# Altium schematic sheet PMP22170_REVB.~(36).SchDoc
size 431 x 279 mm; Date: Not shown in title block; ApprovedBy: Not shown in title block; CheckedBy: Not shown in title block; Author: Not shown in title block; CompanyName: Not shown in title block; Engineer: Not shown in title block; Organization: Not shown in title block; Address1: Not shown in title block; Address2: Not shown in title block; Address3: Not shown in title block; Address4: Not shown in title block; DocumentNumber: 1; Revision: Use project parameter SCH_Rev; SheetNumber: 1; SheetTotal: 1; PageSetup: Record=PageOptions¦CenterHorizontal=True¦CenterVertical=True¦PrintScale=1.00¦XCorrection=1.00¦YCorrection=1.00¦PrintKind=0¦BorderSize=5000000¦LeftOffset=0¦BottomOffset=0¦Orientation=2¦PaperLength=1000¦PaperWidth=1000¦Scale=100¦PaperSource=15¦PrintQuality=600¦MediaType=1¦DitherType=10¦PaperKind=Letter¦PrintScaleMode=1
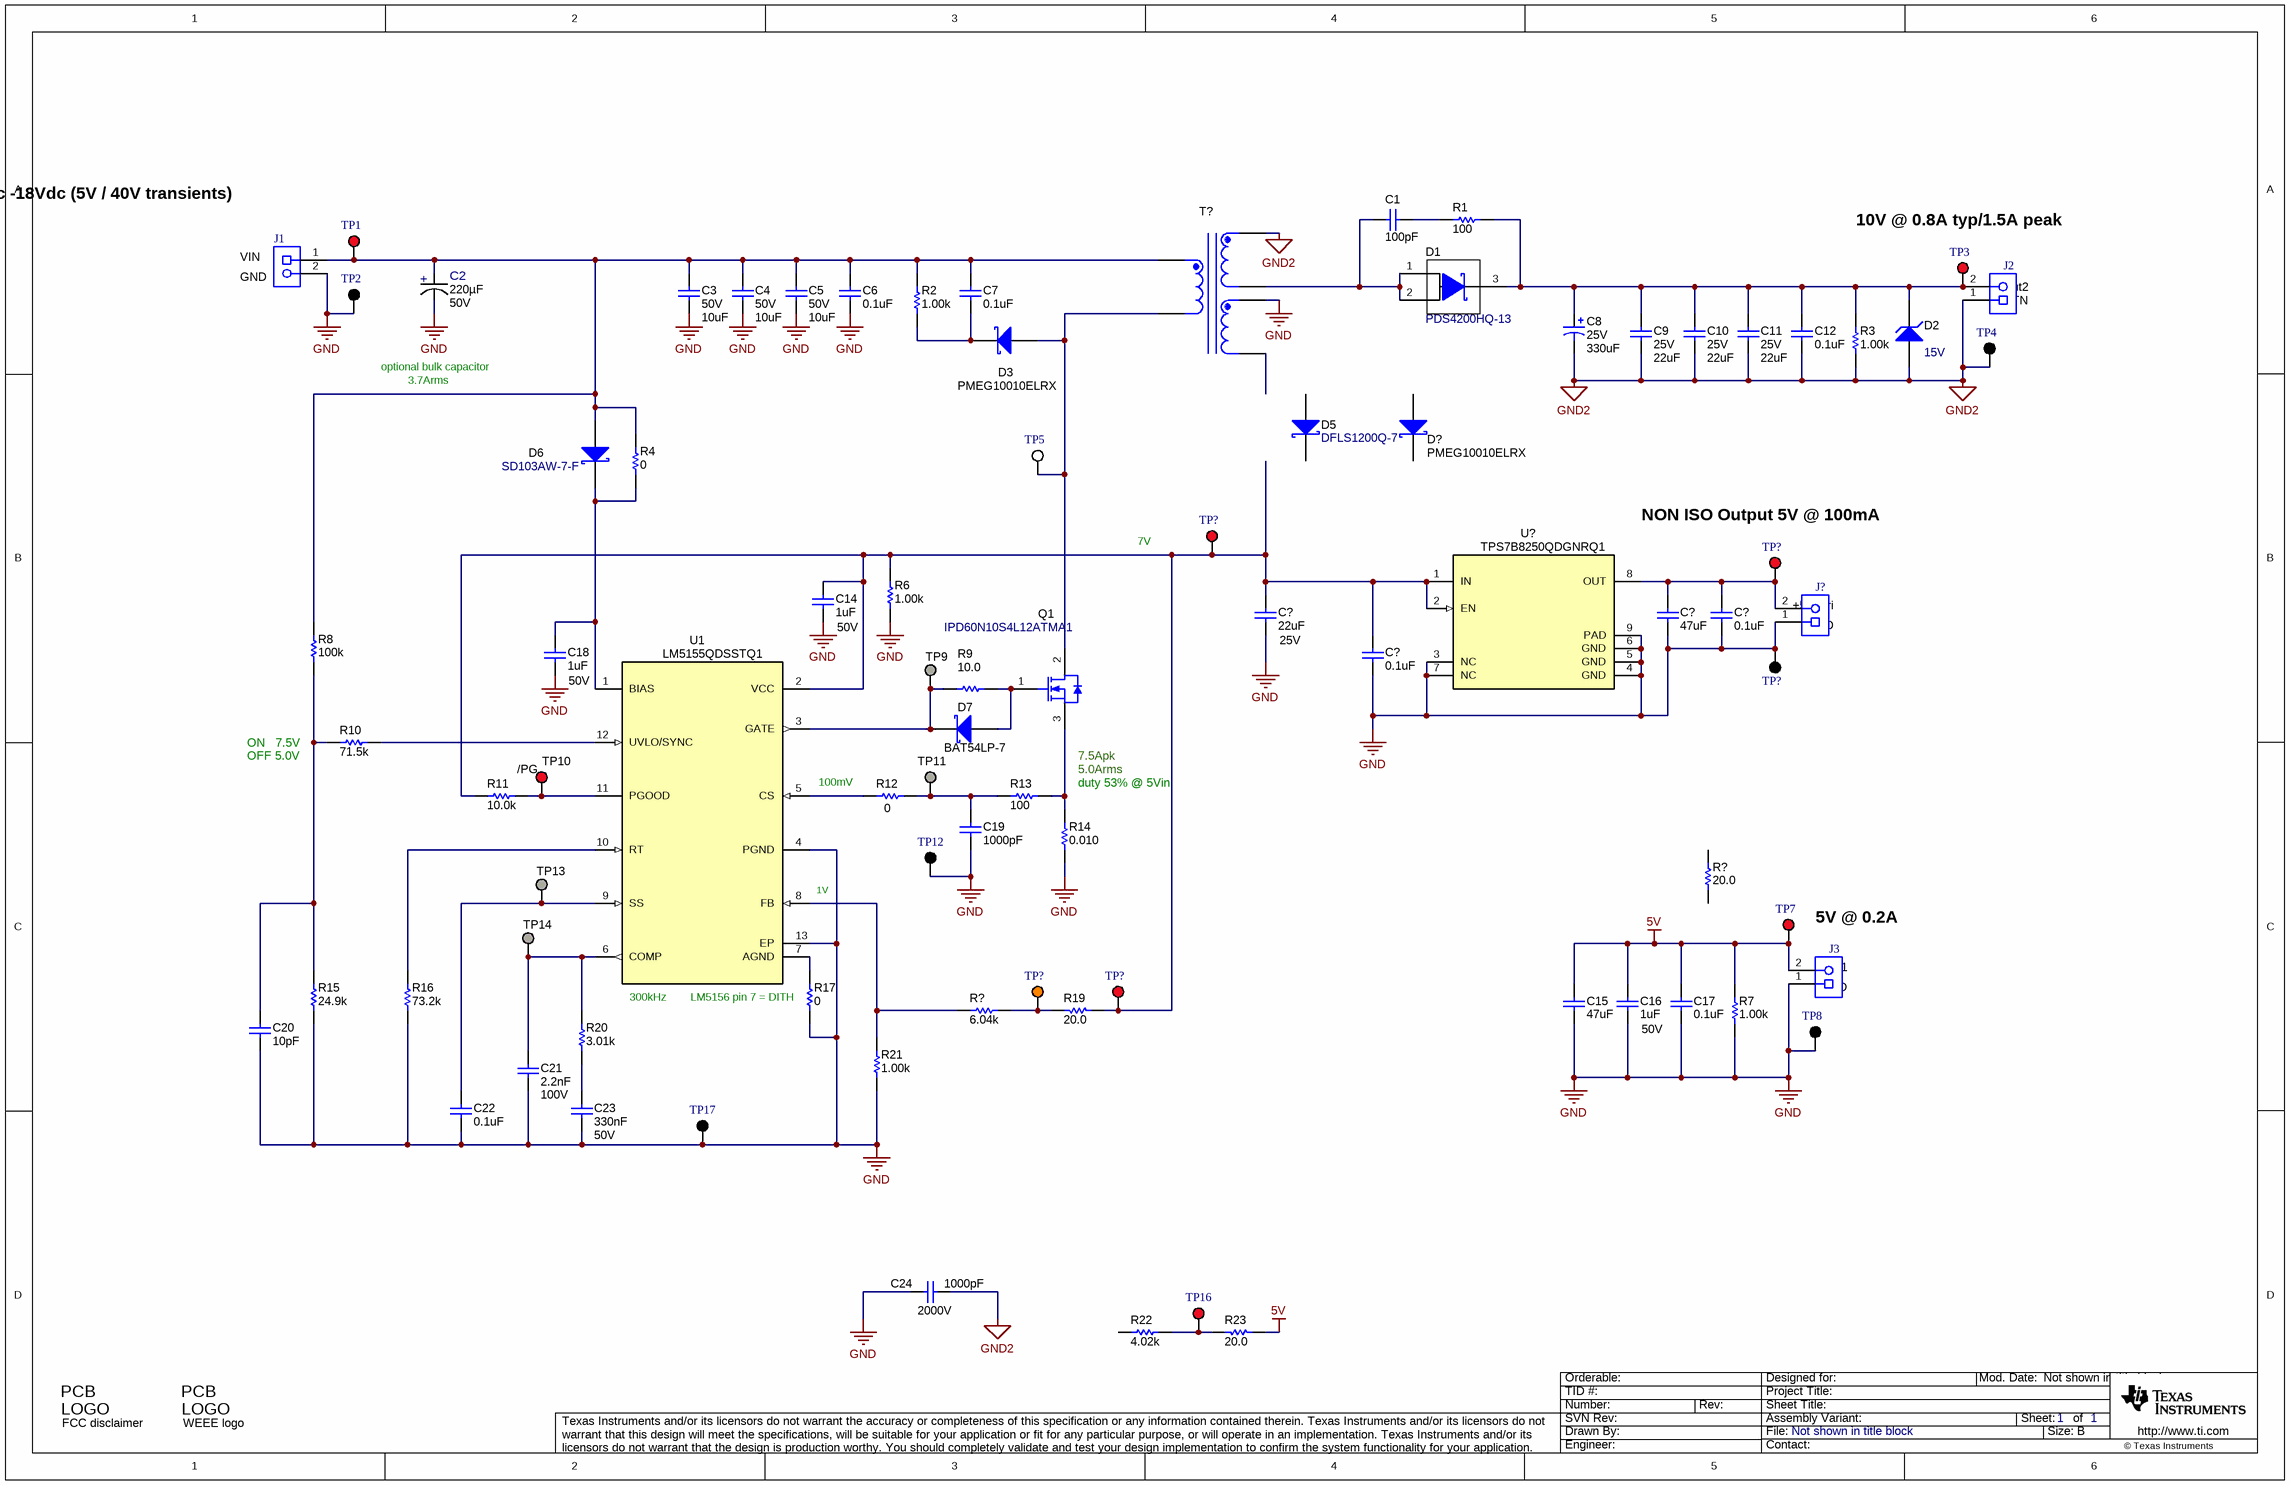
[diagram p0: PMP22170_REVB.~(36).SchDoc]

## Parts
(Parts that share a designator on the sheet are numbered #1, #2 ... from top to bottom, then left to right.)
C1  ValueDisplayed: 100pF  [0805_HV]  (hidden comment: Capacitor)
C2  Cap_F: 220µF  VDC_V: 50V  [FP-EEHZS1H221P_RADIAL_SMD-MFG]  (hidden comment: EEH-ZS1H221V)
C3  VDC_V: 50V  ValueDisplayed: 10uF  [1210_280]  (hidden comment: UMK325AB7106KMHT)
C4  VDC_V: 50V  ValueDisplayed: 10uF  [1210_280]  (hidden comment: UMK325AB7106KMHT)
C5  VDC_V: 50V  ValueDisplayed: 10uF  [1210_280]  (hidden comment: UMK325AB7106KMHT)
C6  ValueDisplayed: 0.1uF  [0603]  (hidden comment: Capacitor)
C7  ValueDisplayed: 0.1uF  [0603]  (hidden comment: Capacitor)
C8  VDC_V: 25V  ValueDisplayed: 330uF  [SM_RADIAL_10BMM]  (hidden comment: EEHZC1E331P)
C9  VDC_V: 25V  ValueDisplayed: 22uF  [1210_270]  (hidden comment: TMK325B7226KMHT)
C10  VDC_V: 25V  ValueDisplayed: 22uF  [1210_270]  (hidden comment: TMK325B7226KMHT)
C11  VDC_V: 25V  ValueDisplayed: 22uF  [1210_270]  (hidden comment: TMK325B7226KMHT)
C12  ValueDisplayed: 0.1uF  [0603]  (hidden comment: Capacitor)
C14  ValueDisplayed: 1uF  Value2: 50V  [0805]  (hidden comment: Capacitor)
C15  ValueDisplayed: 47uF  [1210_270]  (hidden comment: Capacitor)
C16  ValueDisplayed: 1uF  Value2: 50V  [0805]  (hidden comment: Capacitor)
C17  ValueDisplayed: 0.1uF  [0603]  (hidden comment: Capacitor)
C18  ValueDisplayed: 1uF  Value2: 50V  [0805]  (hidden comment: Capacitor)
C19  ValueDisplayed: 1000pF  [0603]  (hidden comment: Capacitor)
C20  ValueDisplayed: 10pF  [0603]  (hidden comment: Capacitor)
C21  Cap_F: 2.2nF  VDC_V: 100V  [0603]  (hidden comment: CGA3E2X7R2A222K080AA)
C22  ValueDisplayed: 0.1uF  [0603]  (hidden comment: Capacitor)
C23  Cap_F: 330nF  VDC_V: 50V  [0603]  (hidden comment: CGA3E3X7R1H334K080AB)
C24  ValueDisplayed: 1000pF  Value2: 2000V  [1808]  (hidden comment: Capacitor)
C?#1  ValueDisplayed: 22uF  Value2: 25V  [1210_270]  (hidden comment: Capacitor)
C?#2  ValueDisplayed: 47uF  [1210_270]  (hidden comment: Capacitor)
C?#3  ValueDisplayed: 0.1uF  [0603]  (hidden comment: Capacitor)
C?#4  ValueDisplayed: 0.1uF  [0603]  (hidden comment: Capacitor)
D1  PDS4200HQ-13  [POWERDI5]
D2  value 15V  [SOD-123]  (hidden comment: MMSZ5245B-7-F)
D3  PartNumber: PMEG10010ELRX  [SOD-123W]  (hidden comment: DIODE_SCHOTTKY)
D5  DFLS1200Q-7  [PowerDI123]
D6  SD103AW-7-F  [SOD-123]
D7  PartNumber: BAT54LP-7  [X1-DFN1006-2]  (hidden comment: DIODE_SCHOTTKY)
D?  PartNumber: PMEG10010ELRX  [SOD-123W]  (hidden comment: DIODE_SCHOTTKY)
J1  Receptacle_2x1  [TERM_BLK_ED555-2DS]  (value not drawn)
J2  Receptacle_2x1  [TERM_BLK_ED555-2DS]  (value not drawn)
J3  Receptacle_2x1  [TERM_BLK_ED555-2DS]  (value not drawn)
J?  Receptacle_2x1  [TERM_BLK_ED555-2DS]  (value not drawn)
Logo1  FCC disclaimer  [FCC_disclaimer]  (no BOM)
Logo2  WEEE logo  [WEEE_Minimum]  (no BOM)
Q1  IPD60N10S4L12ATMA1  [DPAK]
R1  ValueDisplayed: 100  [1206]  (hidden comment: CRCW1206100RFKEAHP)
R2  ValueDisplayed: 1.00k  [1210]  (hidden comment: ERJ14NF1001U)
R3  ValueDisplayed: 1.00k  [1210]  (hidden comment: ERJ14NF1001U)
R4  ValueDisplayed: 0  [0603]  (hidden comment: Resistor)
R6  ValueDisplayed: 1.00k  [1210]  (hidden comment: ERJ14NF1001U)
R7  ValueDisplayed: 1.00k  [1210]  (hidden comment: ERJ14NF1001U)
R8  ValueDisplayed: 100k  [0603]  (hidden comment: CRCW0603100KFKEA)
R9  ValueDisplayed: 10.0  [0603]  (hidden comment: Resistor)
R10  ValueDisplayed: 71.5k  [0603]  (hidden comment: CRCW060371K5FKEA)
R11  ValueDisplayed: 10.0k  [0603]  (hidden comment: CRCW060310K0FKEA)
R12  ValueDisplayed: 0  [0603]  (hidden comment: Resistor)
R13  ValueDisplayed: 100  [0603]  (hidden comment: Resistor)
R14  ValueDisplayed: 0.010  [1206]  (hidden comment: ERJ-8BWFR010V)
R15  ValueDisplayed: 24.9k  [0603]  (hidden comment: CRCW060324K9FKEA)
R16  ValueDisplayed: 73.2k  [0603]  (hidden comment: CRCW060373K2FKEA)
R17  ValueDisplayed: 0  [0603]  (hidden comment: Resistor)
R19  ValueDisplayed: 20.0  [0603]  (hidden comment: CRCW060320R0FKEA)
R20  ValueDisplayed: 3.01k  [0603]  (hidden comment: CRCW06033K01FKEA)
R21  ValueDisplayed: 1.00k  [0603]  (hidden comment: CRCW06031K00FKEA)
R22  ValueDisplayed: 4.02k  [0603]  (hidden comment: CRCW06034K02FKEA)
R23  ValueDisplayed: 20.0  [0603]  (hidden comment: CRCW060320R0FKEA)
R?#1  ValueDisplayed: 20.0  [0805_HV]  (hidden comment: CRCW080520R0FKEA)
R?#2  ValueDisplayed: 6.04k  [0603]  (hidden comment: Resistor)
T?  (no value)  [WURTH_750312924]
TP1  5000  [Keystone5000]  (value not drawn)
TP2  5001  [Keystone5001]  (value not drawn)
TP3  5000  [Keystone5000]  (value not drawn)
TP4  5001  [Keystone5001]  (value not drawn)
TP5  5002  [Keystone5002]  (value not drawn)
TP7  5000  [Keystone5000]  (value not drawn)
TP8  5001  [Keystone5001]  (value not drawn)
TP9  TP_SM_1MM  [TP_SM_1MM]  (value not drawn)  (no BOM)
TP10  5000  [Keystone5000]  (value not drawn)
TP11  TP_SM_1MM  [TP_SM_1MM]  (value not drawn)  (no BOM)
TP12  5001  [Keystone5001]  (value not drawn)
TP13  TP_SM_1MM  [TP_SM_1MM]  (value not drawn)  (no BOM)
TP14  TP_SM_1MM  [TP_SM_1MM]  (value not drawn)  (no BOM)
TP16  5000  [Keystone5000]  (value not drawn)
TP17  5001  [Keystone5001]  (value not drawn)
TP?#1  5000  [Keystone5000]  (value not drawn)
TP?#2  5000  [Keystone5000]  (value not drawn)
TP?#3  5001  [Keystone5001]  (value not drawn)
TP?#4  5003  [Keystone5003]  (value not drawn)
TP?#5  5000  [Keystone5000]  (value not drawn)
U1  LM5155QDSSTQ1  [DSS0012C]
U?  TPS7B8250QDGNRQ1  [DGN0008D_N]

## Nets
5V: C15.1 C16.1 C17.1 J3.2 R7.2 R23.2 TP7.1
GND: C2.1(CATHODE) C3.2 C4.2 C5.2 C6.2 C14.2 C15.2 C16.2 C17.2 C18.2 C19.2 C20.2 C21.2 C22.2 C23.2 C24.2 C?#1.2 C?#2.2 C?#3.2 C?#4.2 J1.2 J3.1 J?.1 R6.1 R7.1 R14.1 R15.1 R16.1 R17.1 R21.1 T?.8 TP2.1 TP8.1 TP12.1 TP17.1 TP?#3.1 U1.4(PGND) U1.13(EP) U?.3(NC) U?.4(GND) U?.5(GND) U?.6(GND) U?.7(NC) U?.9(PAD)
GND2: C8.2(-) C9.2 C10.2 C11.2 C12.2 C24.1 D2.2(A) J2.1 R3.1 T?.6 TP4.1
PG: R11.2 TP10.1 U1.11(PGOOD)
NetC1_1: C1.1 R1.1
NetC1_2: C1.2 D1.1(A) D1.2(A) T?.5
NetC2_2: C2.2(ANODE) C3.1 C4.1 C5.1 C6.1 C7.1 D6.2(A) J1.1 R2.2 R4.2 R8.2 T?.2 TP1.1
NetC7_2: C7.2 D3.1(K) R2.1
NetC8_1: C8.1(+) C9.1 C10.1 C11.1 C12.1 D1.3(K) D2.1(K) J2.2 R1.2 R3.2 TP3.1
NetC14_1: C14.1 C?#1.1 C?#4.1 R6.2 R11.1 R19.2 TP?#1.1 TP?#5.1 U1.2(VCC) U?.1(IN) U?.2(EN)
NetC18_1: C18.1 D6.1(K) R4.1 U1.1(BIAS)
NetC19_1: C19.1 R12.2 R13.1 TP11.1
NetC20_1: C20.1 R8.1 R10.1 R15.2
NetC21_1: C21.1 R20.2 TP14.1 U1.6(COMP)
NetC22_1: C22.1 TP13.1 U1.9(SS)
NetC23_1: C23.1 R20.1
NetC?#2_1: C?#2.1 C?#3.1 J?.2 TP?#2.1 U?.8(OUT)
NetD3_2: D3.2(A) Q1.2(D) T?.3 TP5.1
NetD7_1: D7.1(K) R9.2 TP9.1 U1.3(GATE)
NetD7_2: D7.2(A) Q1.1(G) R9.1
NetQ1_3: Q1.3(S) R13.2 R14.2
NetR10_2: R10.2 U1.12(UVLO/SYNC)
NetR12_1: R12.1 U1.5(CS)
NetR16_2: R16.2 U1.10(RT)
NetR17_2: R17.2 U1.7(AGND)
NetR19_1: R19.1 R?#2.1 TP?#4.1
NetR21_2: R21.2 R?#2.2 U1.8(FB)
NetR22_2: R22.2 R23.1 TP16.1

Not connected (* = marked no-connect by the designer): D5 1(K) 2(A); D? 1(K) 2(A); R22 1; R?#1 1 2; T? 7

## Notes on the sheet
- Input 6Vdc -18Vdc (5V / 40V transients)
- 10V @ 0.8A typ/1.5A peak
- (near J1) VIN
- (near J1) GND
- (near J2) Vout2
- RTN
- optional bulk capacitor
- 3.7Arms
- 7V
- NON ISO Output 5V @ 100mA
- (near J?) +5V0pri
- (near J?) GND
- (near R10) ON   7.5V
- (near R10) OFF 5.0V
- (near TP10) /PG
- 7.5Apk
- 5.0Arms
- 100mV
- duty 53% @ 5Vin
- (near U1) 1V
- 5V @ 0.2A
- (near J3) Vout1
- 300kHz
- (near R17) LM5156 pin 7 = DITH
- (near J3) GND

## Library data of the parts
C1 = CMP-0008236-2: CAP, CERM, 100 pF, 250 V, +/- 5%, C0G/NP0, 0805; PartNumber: GRM21A5C2E101JW01D; Manufacturer: MuRata; Polarized: N; Value: 100pF; U/M: EA; Value1: Unknown; VDC_V: 250V; TaMin_C: -55°C; TaMax_C: 125°C; Cap_Case: 0805; SizeArea_mm2: 2.5; SizeAreaWB_mm2: 6.75; SizeX_mm: 2; SizeY_mm: 1.25; SizeZ_mm: 1.45; AEC Category: Q200
C2 = CMP-0087071-1: 220µF 50V Aluminum Polymer Capacitor Radial, Can - SMD 13 mOhm 4000 Hrs @ 125°C; Manufacturer: Panasonic; SizeZ_mm: 16.8mm; AEC Grade: Grade 1; Symbol Name: SYM-EEHZS1H221P; IRMS_A: 3.7A; Tolerance_%: 20%; AEC Qualified: Yes
C3-C5 = CMP-0009258-2: CAP, CERM, 10 uF, 50 V, +/- 10%, X7R, AEC-Q200 Grade 1, 1210; Manufacturer: Taiyo Yuden; TaMin_C: -55°C; Polarized: N; SizeAreaWB_mm2: 14.7; Value1: Unknown; U/M: EA; Value: 10uF; TaMax_C: 125°C; SizeZ_mm: 2.8; SizeX_mm: 3.2; SizeY_mm: 2.5; Cap_Case: 1210; SizeArea_mm2: 8; AEC Qualified: Y; Cap_F: 10µF; AEC Grade: 1; AEC Category: Q200
C6 C7 C12 = CMP-0007144-4: CAP, CERM, 0.1 uF, 50 V, +/- 10%, X7R, 0603; PartNumber: GCM188R71H104KA57D; Manufacturer: MuRata; Polarized: N; Value: 0.1uF; U/M: EA; Cap_F: 100nF; ESR_ohm: 0.02; Value1: 0.02 ohm; VDC_V: 50V; IRMS_A: 1.84A; TaMin_C: -55°C; TaMax_C: 125°C; AEC Category: Q200; SizeArea_mm2: 1.28; SizeAreaWB_mm2: 4.68; SizeX_mm: 1.6; SizeY_mm: 0.8; SizeZ_mm: 1
C8 = CMP-0012593-3: CAP, Polymer Hybrid, 330 uF, 25 V, +/- 20%, 20 mohm, 10x10 SMD; Manufacturer: Panasonic; TaMin_C: -55°C; ESR_ohm: 20; Polarized: Y; SizeAreaWB_mm2: 159.9; Value1: 20 ohm; Value: 330uF; TaMax_C: 125°C; SizeZ_mm: 10.2; SizeX_mm: 11; SizeY_mm: 10.3; SizeArea_mm2: 113.3; CompType: Capacitor; Cap_F: 330µF; IRMS_A: 2A; AEC Category: Q200
C9-C11 = CMP-0009255-2: CAP, CERM, 22 uF, 25 V, +/- 10%, X7R, AEC-Q200 Grade 1, 1210; Manufacturer: Taiyo Yuden; TaMin_C: -55°C; Polarized: N; SizeAreaWB_mm2: 14.7; Value1: Unknown; U/M: EA; Value: 22uF; TaMax_C: 125°C; SizeZ_mm: 2.7; SizeX_mm: 3.2; SizeY_mm: 2.5; Cap_Case: 1210; SizeArea_mm2: 8; AEC Qualified: Y; Cap_F: 22µF; AEC Grade: 1; AEC Category: Q200
C14 C16 C18 = CMP-0008350-2: CAP, CERM, 1 uF, 50 V, +/- 10%, X7R, 0805; PartNumber: GRM21BR71H105KA12L; Manufacturer: MuRata; Polarized: N; Value: 1uF; U/M: EA; Cap_F: 1µF; Value1: Unknown; TaMin_C: -55°C; TaMax_C: 125°C; SizeArea_mm2: 2.5; SizeAreaWB_mm2: 6.75; SizeX_mm: 2; SizeY_mm: 1.25; SizeZ_mm: 1.45; AEC Category: Q200
C15 C?#2 = CMP-0009220-2: CAP, CERM, 47 uF, 10 V, +/- 10%, X7R, 1210; PartNumber: GRM32ER71A476KE15L; Manufacturer: MuRata; Polarized: N; Value: 47uF; U/M: EA; Cap_F: 47µF; Value1: Unknown; VDC_V: 10V; TaMin_C: -55°C; TaMax_C: 125°C; Cap_Case: 1210; SizeArea_mm2: 8; SizeAreaWB_mm2: 14.7; SizeX_mm: 3.2; SizeY_mm: 2.5; SizeZ_mm: 2.7; AEC Category: Q200
C17 C22 C?#3 C?#4 = CMP-0007378-5: CAP, CERM, 0.1 uF, 16 V, +/- 10%, X7R, 0603; PartNumber: GRM188R71C104KA01D; Manufacturer: MuRata; Polarized: N; Value: 0.1uF; U/M: EA; Cap_F: 100nF; Value1: Unknown; VDC_V: 16V; TaMin_C: -55°C; TaMax_C: 125°C; SizeArea_mm2: 1.28; SizeAreaWB_mm2: 4.68; SizeX_mm: 1.6; SizeY_mm: 0.8; SizeZ_mm: 1; AEC Category: Q200
C19 = CMP-0007402-4: CAP, CERM, 1000 pF, 25 V, +/- 10%, X7R, 0603; PartNumber: GRM188R71E102KA01D; Manufacturer: MuRata; Polarized: N; Value: 1000pF; U/M: EA; Cap_F: 1nF; Value1: Unknown; VDC_V: 25V; TaMin_C: -55°C; TaMax_C: 125°C; SizeArea_mm2: 1.28; SizeAreaWB_mm2: 4.68; SizeX_mm: 1.6; SizeY_mm: 0.8; SizeZ_mm: 1; AEC Category: Q200
C20 = CMP-0007170-4: CAP, CERM, 10 pF, 50 V, +/- 5%, C0G/NP0, 0603; PartNumber: GRM1885C1H100JA01D; Manufacturer: MuRata; Polarized: N; Value: 10pF; U/M: EA; Value1: Unknown; VDC_V: 50V; TaMin_C: -55°C; TaMax_C: 125°C; SizeArea_mm2: 1.28; SizeAreaWB_mm2: 4.68; SizeX_mm: 1.6; SizeY_mm: 0.8; SizeZ_mm: 1; AEC Category: Q200
C21 = CMP-0007085-4: CAP, CERM, 2200 pF, 100 V, +/- 10%, X7R, AEC-Q200 Grade 1, 0603; Manufacturer: TDK; TaMin_C: -55°C; ESR_ohm: 0.923948; Polarized: N; SizeAreaWB_mm2: 4.68; Value1: 0.923948 ohm; U/M: EA; Value: 2200pF; TaMax_C: 125°C; SizeZ_mm: 1; SizeX_mm: 1.6; SizeY_mm: 0.8; SizeArea_mm2: 1.28; AEC Qualified: Y; IRMS_A: 295.638mA; AEC Category: Q200
C23 = CMP-0007095-4: CAP, CERM, 0.33 uF, 50 V, +/- 10%, X7R, AEC-Q200 Grade 1, 0603; Manufacturer: TDK; TaMin_C: -55°C; ESR_ohm: 0.01584; Polarized: N; SizeAreaWB_mm2: 4.68; Value1: 0.01584 ohm; U/M: EA; Value: 0.33uF; TaMax_C: 125°C; SizeZ_mm: 1; SizeX_mm: 1.6; SizeY_mm: 0.8; SizeArea_mm2: 1.28; AEC Qualified: Y; IRMS_A: 1.31353A; AEC Category: Q200
C24 = CMP-0009436-2: CAP, CERM, 1000 pF, 2000 V, +/- 10%, X7R, 1808; PartNumber: GR442QR73D102KW01L; Manufacturer: MuRata; Polarized: N; Value: 1000pF; U/M: EA; Cap_F: 1nF; Value1: Unknown; VDC_V: 2kV; TaMin_C: -55°C; TaMax_C: 125°C; SizeArea_mm2: 9; SizeAreaWB_mm2: 16.5; SizeX_mm: 4.5; SizeY_mm: 2; SizeZ_mm: 2.03; AEC Category: Q200
C?#1 = CMP-0009224-2: CAP, CERM, 22 uF, 25 V, +/- 10%, X7R, 1210; PartNumber: GRM32ER71E226KE15L; Manufacturer: MuRata; Polarized: N; Value: 22uF; U/M: EA; Cap_F: 22µF; Value1: Unknown; TaMin_C: -55°C; TaMax_C: 125°C; Cap_Case: 1210; SizeArea_mm2: 8; SizeAreaWB_mm2: 14.7; SizeX_mm: 3.2; SizeY_mm: 2.5; SizeZ_mm: 2.7; AEC Category: Q200
D1 = CMP-0081019-2: Diode, Schottky, 200 V, 4 A, AEC-Q101, PowerDI5; Manufacturer: Diodes Inc.; Vf_V: 840mV; Io_A: 4A; SizeX_mm: 6.4; Vr_V: 200V; Value2: 0.84V; AEC Category: Q101; TJmax_C: 175°C; SizeAreaWB_mm2: 49.56; SizeArea_mm2: 24.96; Value: 200V; AEC Qualified: Y; SizeY_mm: 3.9; SizeZ_mm: 1.05
D2 = CMP-0005753-1: Diode, Zener, 15 V, 500 mW, SOD-123; Manufacturer: Diodes Inc.; Power_W: 500mW; SizeAreaWB_mm2: 13.095; Value1: 0.5W; RJA_CperW: 350; U/M: EA; SizeZ_mm: 1.35; SizeX_mm: 3.85; SizeY_mm: 1.7; SizeArea_mm2: 6.545; AEC Category: Q101
D3 D? = CMP-0028782-2: Diode, Schottky, 100 V, 1 A, AEC-Q101, SOD-123W; Manufacturer: Nexperia; Vf_V: 770mV; Value: 100V; Value1: 1A; Value2: 0.77V; TJmax_C: 175°C; SizeAreaWB_mm2: 12.15; SizeArea_mm2: 5.95; SizeX_mm: 3.5; SizeY_mm: 1.7; SizeZ_mm: 1; AEC Category: Q101; AEC Qualified: Y; Green_Lifecycle: Not Set; Green_REACh: Incomplete
D5 = CMP-0028517-2: Diode, Schottky, 200 V, 1 A, PowerDI123; Manufacturer: Diodes Inc.; Vr_V: 200V; SizeZ_mm: 0.98; Value: 200V; TJmax_C: 175°C; SizeY_mm: 1.78; Vf_V: 850mV; Green_REACh: Passed; Io_A: 1A; Value2: 0.85V; SizeAreaWB_mm2: 13.066; SizeArea_mm2: 6.586; Green_Lifecycle: Active; AEC Category: Q101; SizeX_mm: 3.7; RJC_CperW: 7
D6 = CMP-0028543-1: Diode, Schottky, 40 V, 0.35 A, SOD-123; Manufacturer: Diodes Inc.; Io_A: 350mA; Green_Lifecycle: Active; SizeAreaWB_mm2: 13.095; Vr_V: 40V; Green_REACh: Passed; Value1: 0.35A; U/M: EA; Value: 40V; SizeZ_mm: 1.35; SizeX_mm: 3.85; SizeY_mm: 1.7; Vf_V: 550mV; Value2: 0.55V; SizeArea_mm2: 6.545; AEC Category: Q101
D7 = CMP-0076931-2: Diode, Schottky, 30 V, 0.2 A, 1.00x0.50x0.60mm; Manufacturer: Diodes Inc.; Vf_V: 1V; Value: 30V; Value1: 0.2A; Io_A: 200mA; SizeAreaWB_mm2: 3.2; SizeArea_mm2: 0.6; SizeX_mm: 1.0; SizeZ_mm: 0.53; AEC Category: Q101; Green_Lifecycle: Not Set; Green_REACh: Incomplete
J1-J3 J? = CMP-0074913-1: Terminal Block, 3.5mm Pitch, 2x1, TH; PartNumber: ED555/2DS; Manufacturer: On-Shore Technology; Cert_CULUS: Y; CNHeader: False; ContactFinish: Brass; CT: True; Current_A: 6A; Gender: Female; Green_Lifecycle: Active; Green_REACh: Passed; Pitch_mm: 3.5; Row_Count: 1; Shrouded: N; Voltage_V: 150V
Logo1 = CMP-0074847-1: FCC_disclaimer; Library Reference: Logo
Logo2 = CMP-0074769-1
Q1 = CMP-0080670-2: MOSFET, N-CH, 100 V, 60 A, AEC-Q101, DPAK; Manufacturer: Infineon Technologies; Alternate Manufacturer: None; QgTyp_nC: 38; AEC Category: Q101; Vgs_V: 16V; Value1: 0.015 ohm; SizeAreaWB_mm2: 101.7114; IdsMax_A: 60A; SizeX_mm: 9.91; SizeArea_mm2: 64.8114; Value: 100V; Value2: 38 nC; Rdson45_ohm: 0.015; SizeY_mm: 6.54; ChType: N; AEC Qualified: Y; ChMode: Enhancement; SizeZ_mm: 2.29
R1 = CMP-0016570-3: RES, 100, 1%, 0.5 W, AEC-Q200 Grade 0, 1206; Manufacturer: Vishay-Dale; Power_W: 500mW; TempCo: 100 ppm/C; Value_Code: 100R; Value: 100; EIA_Code: E96; SizeX_mm: 3.2; SizeY_mm: 1.6; SizeZ_mm: 1.35; Value2: 0.5W; SizeArea_mm2: 5.12; AEC Qualified: Y; AEC Grade: 0; AEC Category: Q200
R2 R3 R6 R7 = CMP-0015030-3: RES, 1.00 k, 1%, 0.5 W, AEC-Q200 Grade 0, 1210; Manufacturer: Panasonic; Power_W: 500mW; TempCo: 100 ppm/C; SizeAreaWB_mm2: 14.7; Value_Code: 1k00; Value: 1.00k; EIA_Code: E96; Res_ohm: 1k; SizeX_mm: 3.2; SizeY_mm: 2.5; SizeZ_mm: 1.35; Value2: 0.5W; SizeArea_mm2: 8; AEC Qualified: Y; VDC_V: 22V; AEC Category: Q200; AEC Grade: 0
R4 R12 R17 = CMP-0025697-4: RES, 0, 5%, 0.1 W, AEC-Q200 Grade 0, 0603; PartNumber: CRCW06030000Z0EA; Manufacturer: Vishay-Dale; Value: 0; Value_Code: 0000; Power_W: 100mW; Value2: 0.1W; VDC_V: 75V; TempCo: 200 ppm/C; SizeArea_mm2: 1.28; SizeX_mm: 1.6; SizeY_mm: 0.8; SizeZ_mm: 1; EIA_Code: E24; AEC Category: Q200; AEC Qualified: Y
R8 = CMP-0021990-4: RES, 100 k, 1%, 0.1 W, AEC-Q200 Grade 0, 0603; Manufacturer: Vishay-Dale; Power_W: 100mW; TempCo: 100 ppm/C; Value: 100k; EIA_Code: E96; SizeX_mm: 1.6; SizeY_mm: 0.8; SizeZ_mm: 1; Value2: 0.1W; SizeArea_mm2: 1.28; AEC Qualified: Y; VDC_V: 75V; AEC Category: Q200; AEC Grade: 0
R9 = CMP-0022003-4: RES, 10.0, 1%, 0.1 W, AEC-Q200 Grade 0, 0603; PartNumber: CRCW060310R0FKEA; Manufacturer: Vishay-Dale; Value: 10.0; Res_ohm: 10; Value_Code: 10R0; Power_W: 100mW; Value2: 0.1W; VDC_V: 75V; TempCo: 100 ppm/C; SizeArea_mm2: 1.28; SizeX_mm: 1.6; SizeY_mm: 0.8; SizeZ_mm: 1; EIA_Code: E96; AEC Category: Q200; AEC Qualified: Y; AEC Grade: 0
R10 = CMP-0022581-4: RES, 71.5 k, 1%, 0.1 W, AEC-Q200 Grade 0, 0603; Manufacturer: Vishay-Dale; Power_W: 100mW; TempCo: 100 ppm/C; Value_Code: 71k5; Value: 71.5k; EIA_Code: E96; SizeX_mm: 1.6; SizeY_mm: 0.8; SizeZ_mm: 1; Value2: 0.1W; SizeArea_mm2: 1.28; AEC Qualified: Y; VDC_V: 75V; AEC Category: Q200; AEC Grade: 0
R11 = CMP-0021998-4: RES, 10.0 k, 1%, 0.1 W, AEC-Q200 Grade 0, 0603; Manufacturer: Vishay-Dale; Power_W: 100mW; TempCo: 100 ppm/C; Value_Code: 10k0; Value: 10.0k; EIA_Code: E96; Res_ohm: 10k; SizeX_mm: 1.6; SizeY_mm: 0.8; SizeZ_mm: 1; Value2: 0.1W; SizeArea_mm2: 1.28; AEC Qualified: Y; VDC_V: 75V; AEC Category: Q200; AEC Grade: 0
R13 = CMP-0021991-4: RES, 100, 1%, 0.1 W, AEC-Q200 Grade 0, 0603; PartNumber: CRCW0603100RFKEA; Manufacturer: Vishay-Dale; Value: 100; Value_Code: 100R; Power_W: 100mW; Value2: 0.1W; VDC_V: 75V; TempCo: 100 ppm/C; SizeArea_mm2: 1.28; SizeX_mm: 1.6; SizeY_mm: 0.8; SizeZ_mm: 1; EIA_Code: E96; AEC Category: Q200; AEC Qualified: Y; AEC Grade: 0
R14 = CMP-0750151-1: RES, 0.010, 1%, 1 W, AEC-Q200 Grade 0, 1206; Manufacturer: Panasonic; SizeZ_mm: 1.35; Value_Code: R010; Value2: 1W; AEC Category: Q200; Value: 0.010; SizeAreaWB_mm2: 10.92; TempCo: 200 ppm/C; SizeY_mm: 1.6; SizeArea_mm2: 5.12; SizeX_mm: 3.2; AEC Grade: 0; EIA_Code: E96; AEC Qualified: Y
R15 = CMP-0022237-4: RES, 24.9 k, 1%, 0.1 W, AEC-Q200 Grade 0, 0603; Manufacturer: Vishay-Dale; Power_W: 100mW; TempCo: 100 ppm/C; Value_Code: 24k9; Value: 24.9k; EIA_Code: E96; SizeX_mm: 1.6; SizeY_mm: 0.8; SizeZ_mm: 1; Value2: 0.1W; SizeArea_mm2: 1.28; AEC Qualified: Y; VDC_V: 75V; AEC Category: Q200; AEC Grade: 0
R16 = CMP-0022585-4: RES, 73.2 k, 1%, 0.1 W, AEC-Q200 Grade 0, 0603; Manufacturer: Vishay-Dale; Power_W: 100mW; TempCo: 100 ppm/C; Value_Code: 73k2; Value: 73.2k; EIA_Code: E96; SizeX_mm: 1.6; SizeY_mm: 0.8; SizeZ_mm: 1; Value2: 0.1W; SizeArea_mm2: 1.28; AEC Qualified: Y; VDC_V: 75V; AEC Category: Q200; AEC Grade: 0
R19 R23 = CMP-0022206-4: RES, 20.0, 1%, 0.1 W, AEC-Q200 Grade 0, 0603; Manufacturer: Vishay-Dale; Power_W: 100mW; TempCo: 100 ppm/C; Value_Code: 20R0; Value: 20.0; EIA_Code: E96; Res_ohm: 20; SizeX_mm: 1.6; SizeY_mm: 0.8; SizeZ_mm: 1; Value2: 0.1W; SizeArea_mm2: 1.28; AEC Qualified: Y; VDC_V: 75V; AEC Category: Q200; AEC Grade: 0
R20 = CMP-0022371-4: RES, 3.01 k, 1%, 0.1 W, AEC-Q200 Grade 0, 0603; Manufacturer: Vishay-Dale; Power_W: 100mW; TempCo: 100 ppm/C; Value_Code: 3k01; Value: 3.01k; EIA_Code: E96; SizeX_mm: 1.6; SizeY_mm: 0.8; SizeZ_mm: 1; Value2: 0.1W; SizeArea_mm2: 1.28; AEC Qualified: Y; VDC_V: 75V; AEC Category: Q200; AEC Grade: 0
R21 = CMP-0022109-5: RES, 1.00 k, 1%, 0.1 W, AEC-Q200 Grade 0, 0603; Manufacturer: Vishay-Dale; Power_W: 100mW; TempCo: 100 ppm/C; Value_Code: 1k00; Value: 1.00k; EIA_Code: E96; Res_ohm: 1k; SizeX_mm: 1.6; SizeY_mm: 0.8; SizeZ_mm: 1; Value2: 0.1W; SizeArea_mm2: 1.28; AEC Qualified: Y; VDC_V: 75V; AEC Category: Q200; AEC Grade: 0
R22 = CMP-0022449-4: RES, 4.02 k, 1%, 0.1 W, AEC-Q200 Grade 0, 0603; Manufacturer: Vishay-Dale; Power_W: 100mW; TempCo: 100 ppm/C; Value_Code: 4k02; Value: 4.02k; EIA_Code: E96; SizeX_mm: 1.6; SizeY_mm: 0.8; SizeZ_mm: 1; Value2: 0.1W; SizeArea_mm2: 1.28; AEC Qualified: Y; VDC_V: 75V; AEC Category: Q200; AEC Grade: 0
R?#1 = CMP-0021044-3: RES, 20.0, 1%, 0.125 W, AEC-Q200 Grade 0, 0805; Manufacturer: Vishay-Dale; Power_W: 125mW; Value_Code: 20R0; TempCo: 100 ppm/C; Value: 20.0; EIA_Code: E96; Res_ohm: 20; SizeX_mm: 2; SizeY_mm: 1.25; SizeZ_mm: 1.45; Value2: 0.125W; SizeArea_mm2: 2.5; AEC Qualified: Y; VDC_V: 150V; AEC Category: Q200; AEC Grade: 0
R?#2 = CMP-0022558-4: RES, 6.04 k, 1%, 0.1 W, AEC-Q200 Grade 0, 0603; PartNumber: CRCW06036K04FKEA; Manufacturer: Vishay-Dale; Value: 6.04k; Value_Code: 6k04; Power_W: 100mW; Value2: 0.1W; VDC_V: 75V; TempCo: 100 ppm/C; SizeArea_mm2: 1.28; SizeX_mm: 1.6; SizeY_mm: 0.8; SizeZ_mm: 1; EIA_Code: E96; AEC Category: Q200; AEC Qualified: Y; AEC Grade: 0
T? = CMP-0030533-1: Transformer, 7 uH, SMT; Manufacturer: Wurth Elektronik; PartNumber: TBD
TP1 TP3 TP7 TP10 TP16 TP?#1 TP?#2 TP?#5 = CMP-0055137-1: Test Point, Miniature, Red, TH; Manufacturer: Keystone; CNHeader: FALSE; ContactFinish: Silver; CT: TRUE; Green_Lifecycle: Active; Green_REACh: Passed
TP2 TP4 TP8 TP12 TP17 TP?#3 = CMP-0055138-1: Test Point, Miniature, Black, TH; Manufacturer: Keystone; CNHeader: FALSE; ContactFinish: Silver; CT: TRUE; Green_Lifecycle: Active; Green_REACh: Passed
TP5 = CMP-0055139-1: Test Point, Miniature, White, TH; Manufacturer: Keystone; ContactFinish: Silver; CNHeader: FALSE; CT: TRUE; Green_Lifecycle: Active; Green_REACh: Passed
TP9 TP11 TP13 TP14 = CMP-0003825-1: 1mm Test Point, SMT; Manufacturer: Any
TP?#4 = CMP-0055140-1: Test Point, Miniature, Orange, TH; Manufacturer: Keystone; ContactFinish: Silver; CNHeader: FALSE; CT: TRUE; Green_Lifecycle: Active; Green_REACh: Passed
U1 = CMP-0081538-1: Automotive Grade 2.2-MHz Wide Input Non-synchronous Boost Controller, DSS0012C (WSON-12); Alternate PartNumber: LM5155QDSSRQ1; Alternate Manufacturer: Texas Instruments; SizeAreaWB_mm2: 12; SizeZ_mm: 0.8; SizeX_mm: 2; SizeY_mm: 3; SizeArea_mm2: 6; CompType: IC; AEC Qualified: Y; AEC Category: Q200
U? = CMP-0013313-4: 300mA High-Voltage Ultra-Low-Iq Low-Dropout (LDO) Regulator, DGN0008D (VSSOP-8); Manufacturer: Texas Instruments; SizeX_mm: 5.05; SizeY_mm: 3.1; CompType: IC; SizeZ_mm: 1.1; SizeArea_mm2: 15.655; SizeAreaWB_mm2: 35.955; AEC Category: Q200; AEC Qualified: Y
